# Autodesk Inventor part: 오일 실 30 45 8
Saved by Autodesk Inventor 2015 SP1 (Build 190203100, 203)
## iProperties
Created: 2026-07
Part Number: 오일 실 30 45 8
Material: 일반
Document SubType Name: Modeling
Designer: user
Density: 1 g/cm^3
Appearance: 기본값
Author: user
Author: jhkim
Creation Date: 2026-07-01
Sending System: Autodesk Inventor 2027
Preprocessor: ST-DEVELOPER v20.1
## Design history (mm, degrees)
node "오일 실 30 45 81"
body "Solid1"
node "기준1"
